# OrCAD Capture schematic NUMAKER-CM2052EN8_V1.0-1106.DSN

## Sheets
1 Nu-Link2-Me: size A3; title: Nu-Link2-Me; rev: 1.0; company: CMHuang; note: Nu-Link2-Me
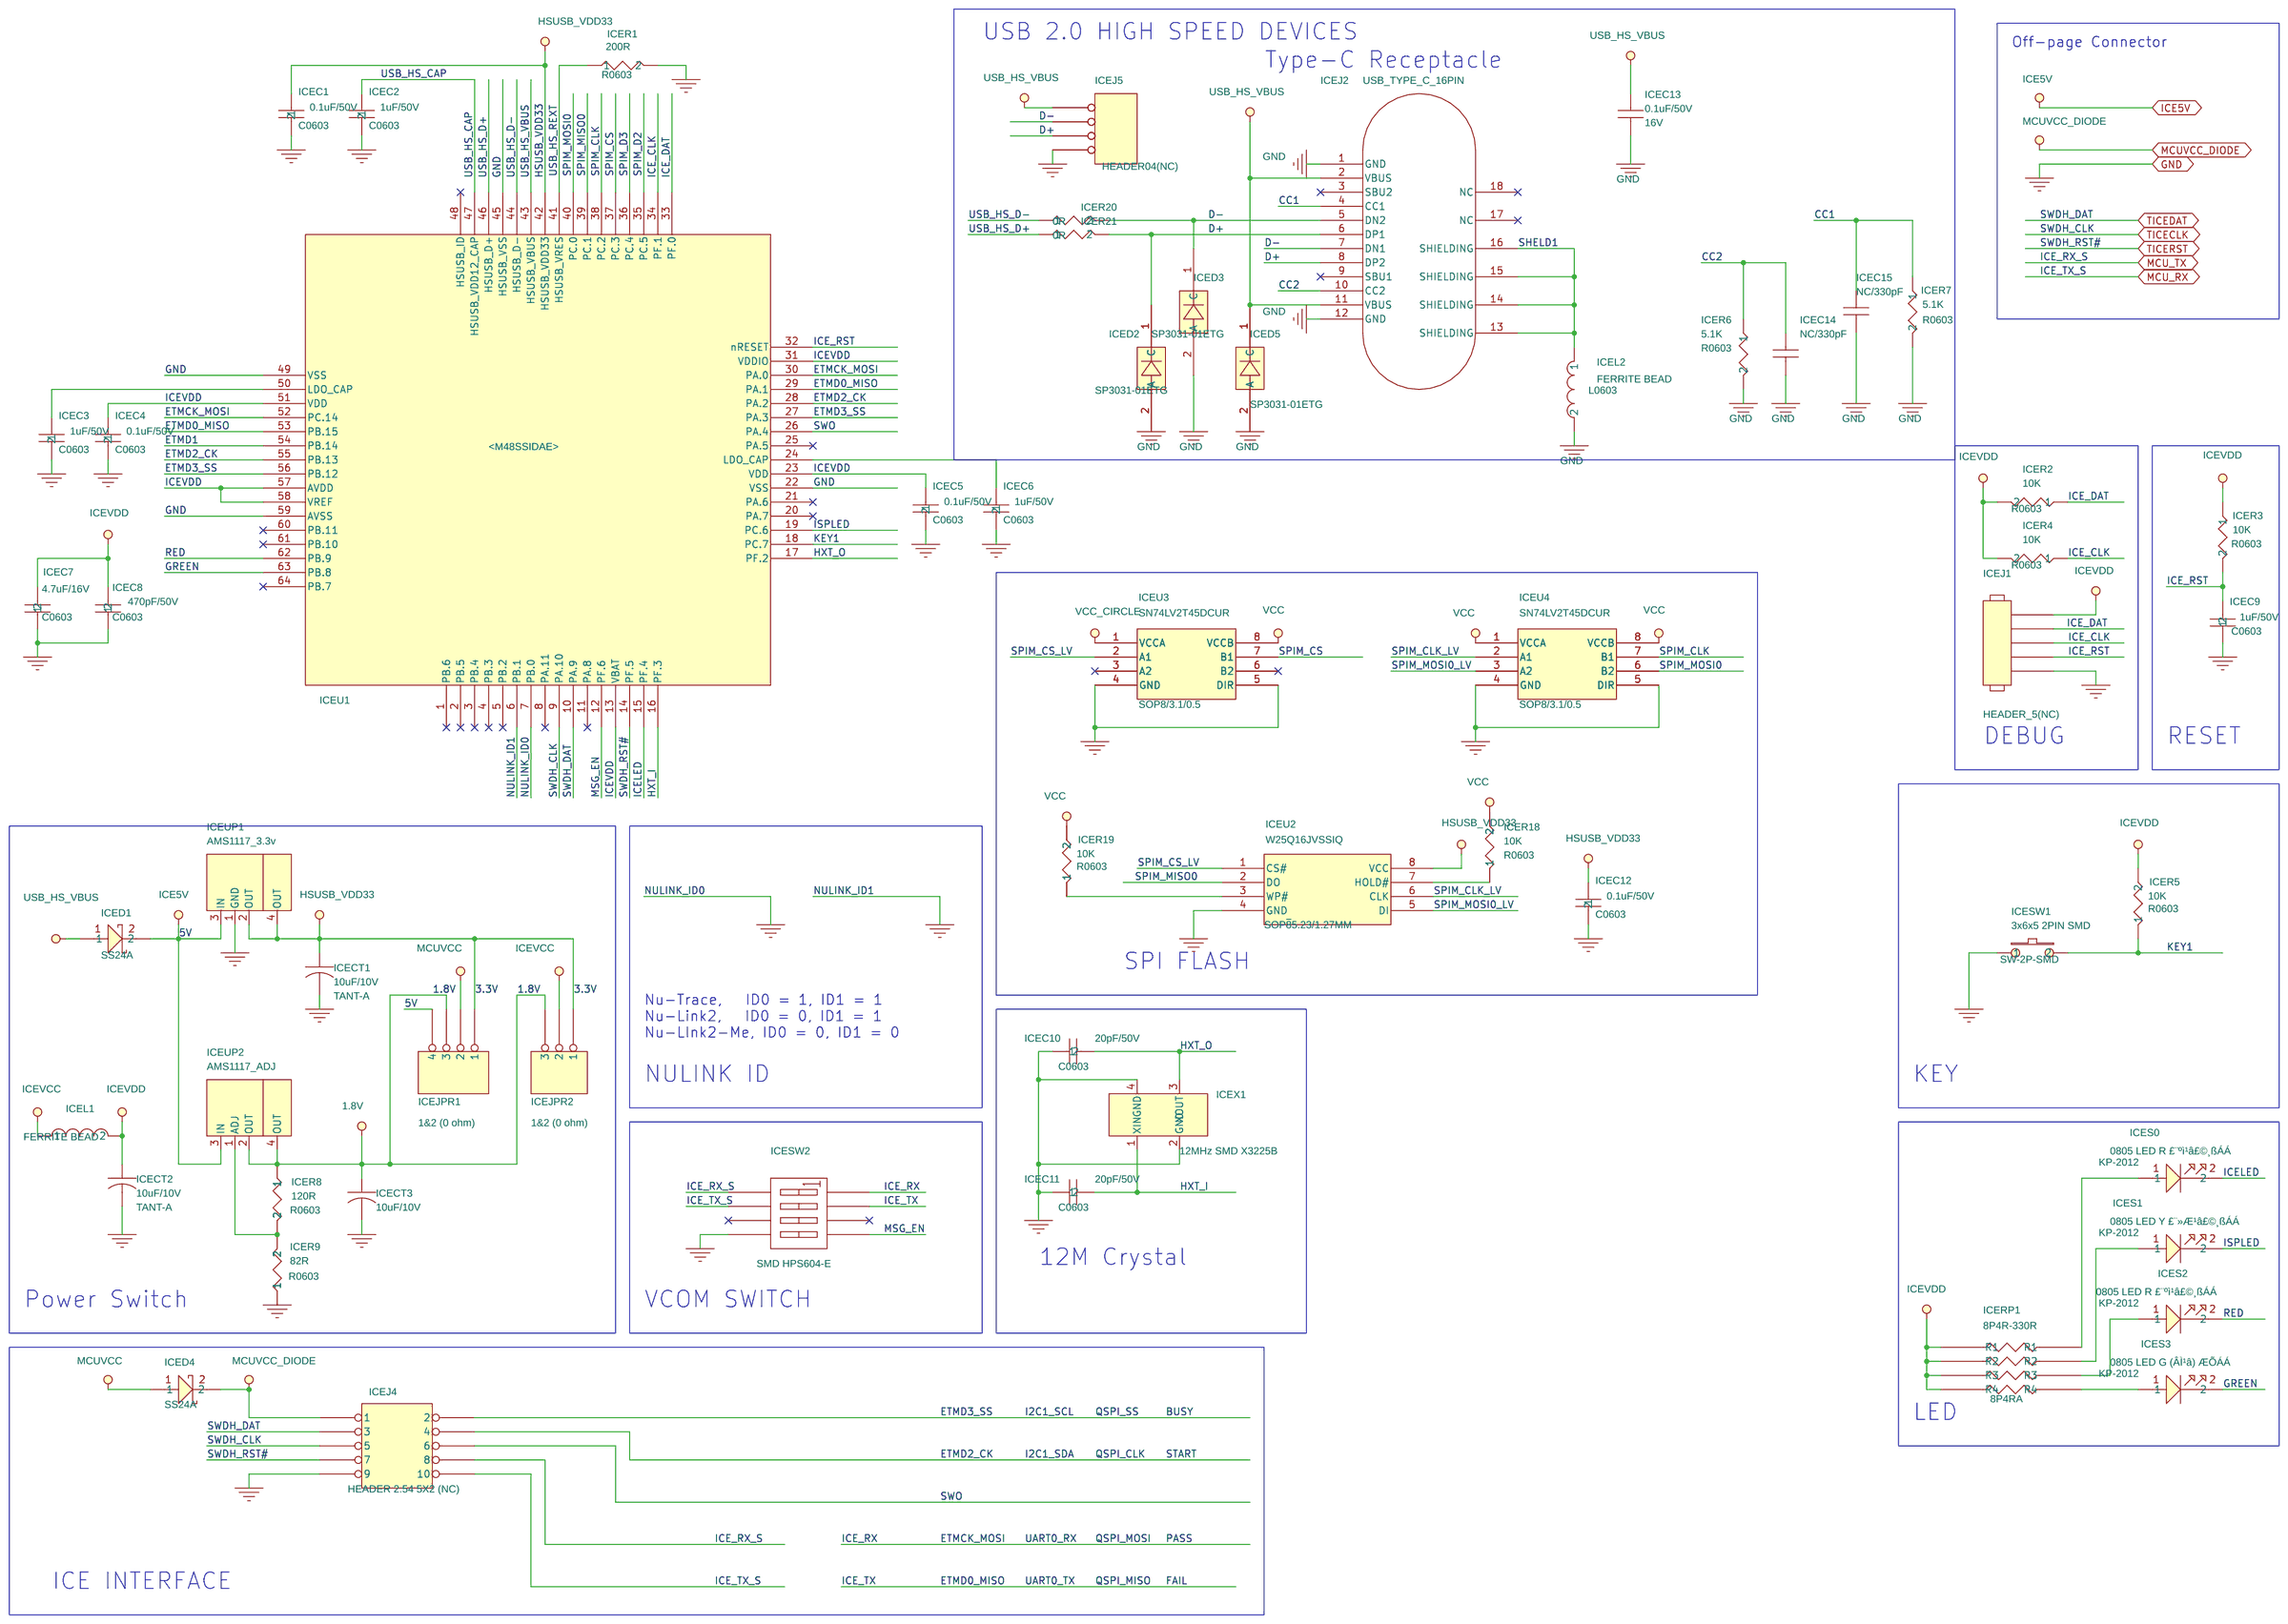
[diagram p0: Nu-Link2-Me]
2 CM2052EN8: size Custom; title: CM2052EN8; rev: v1.0; note: NuMaker-PFM-CM2052EN8
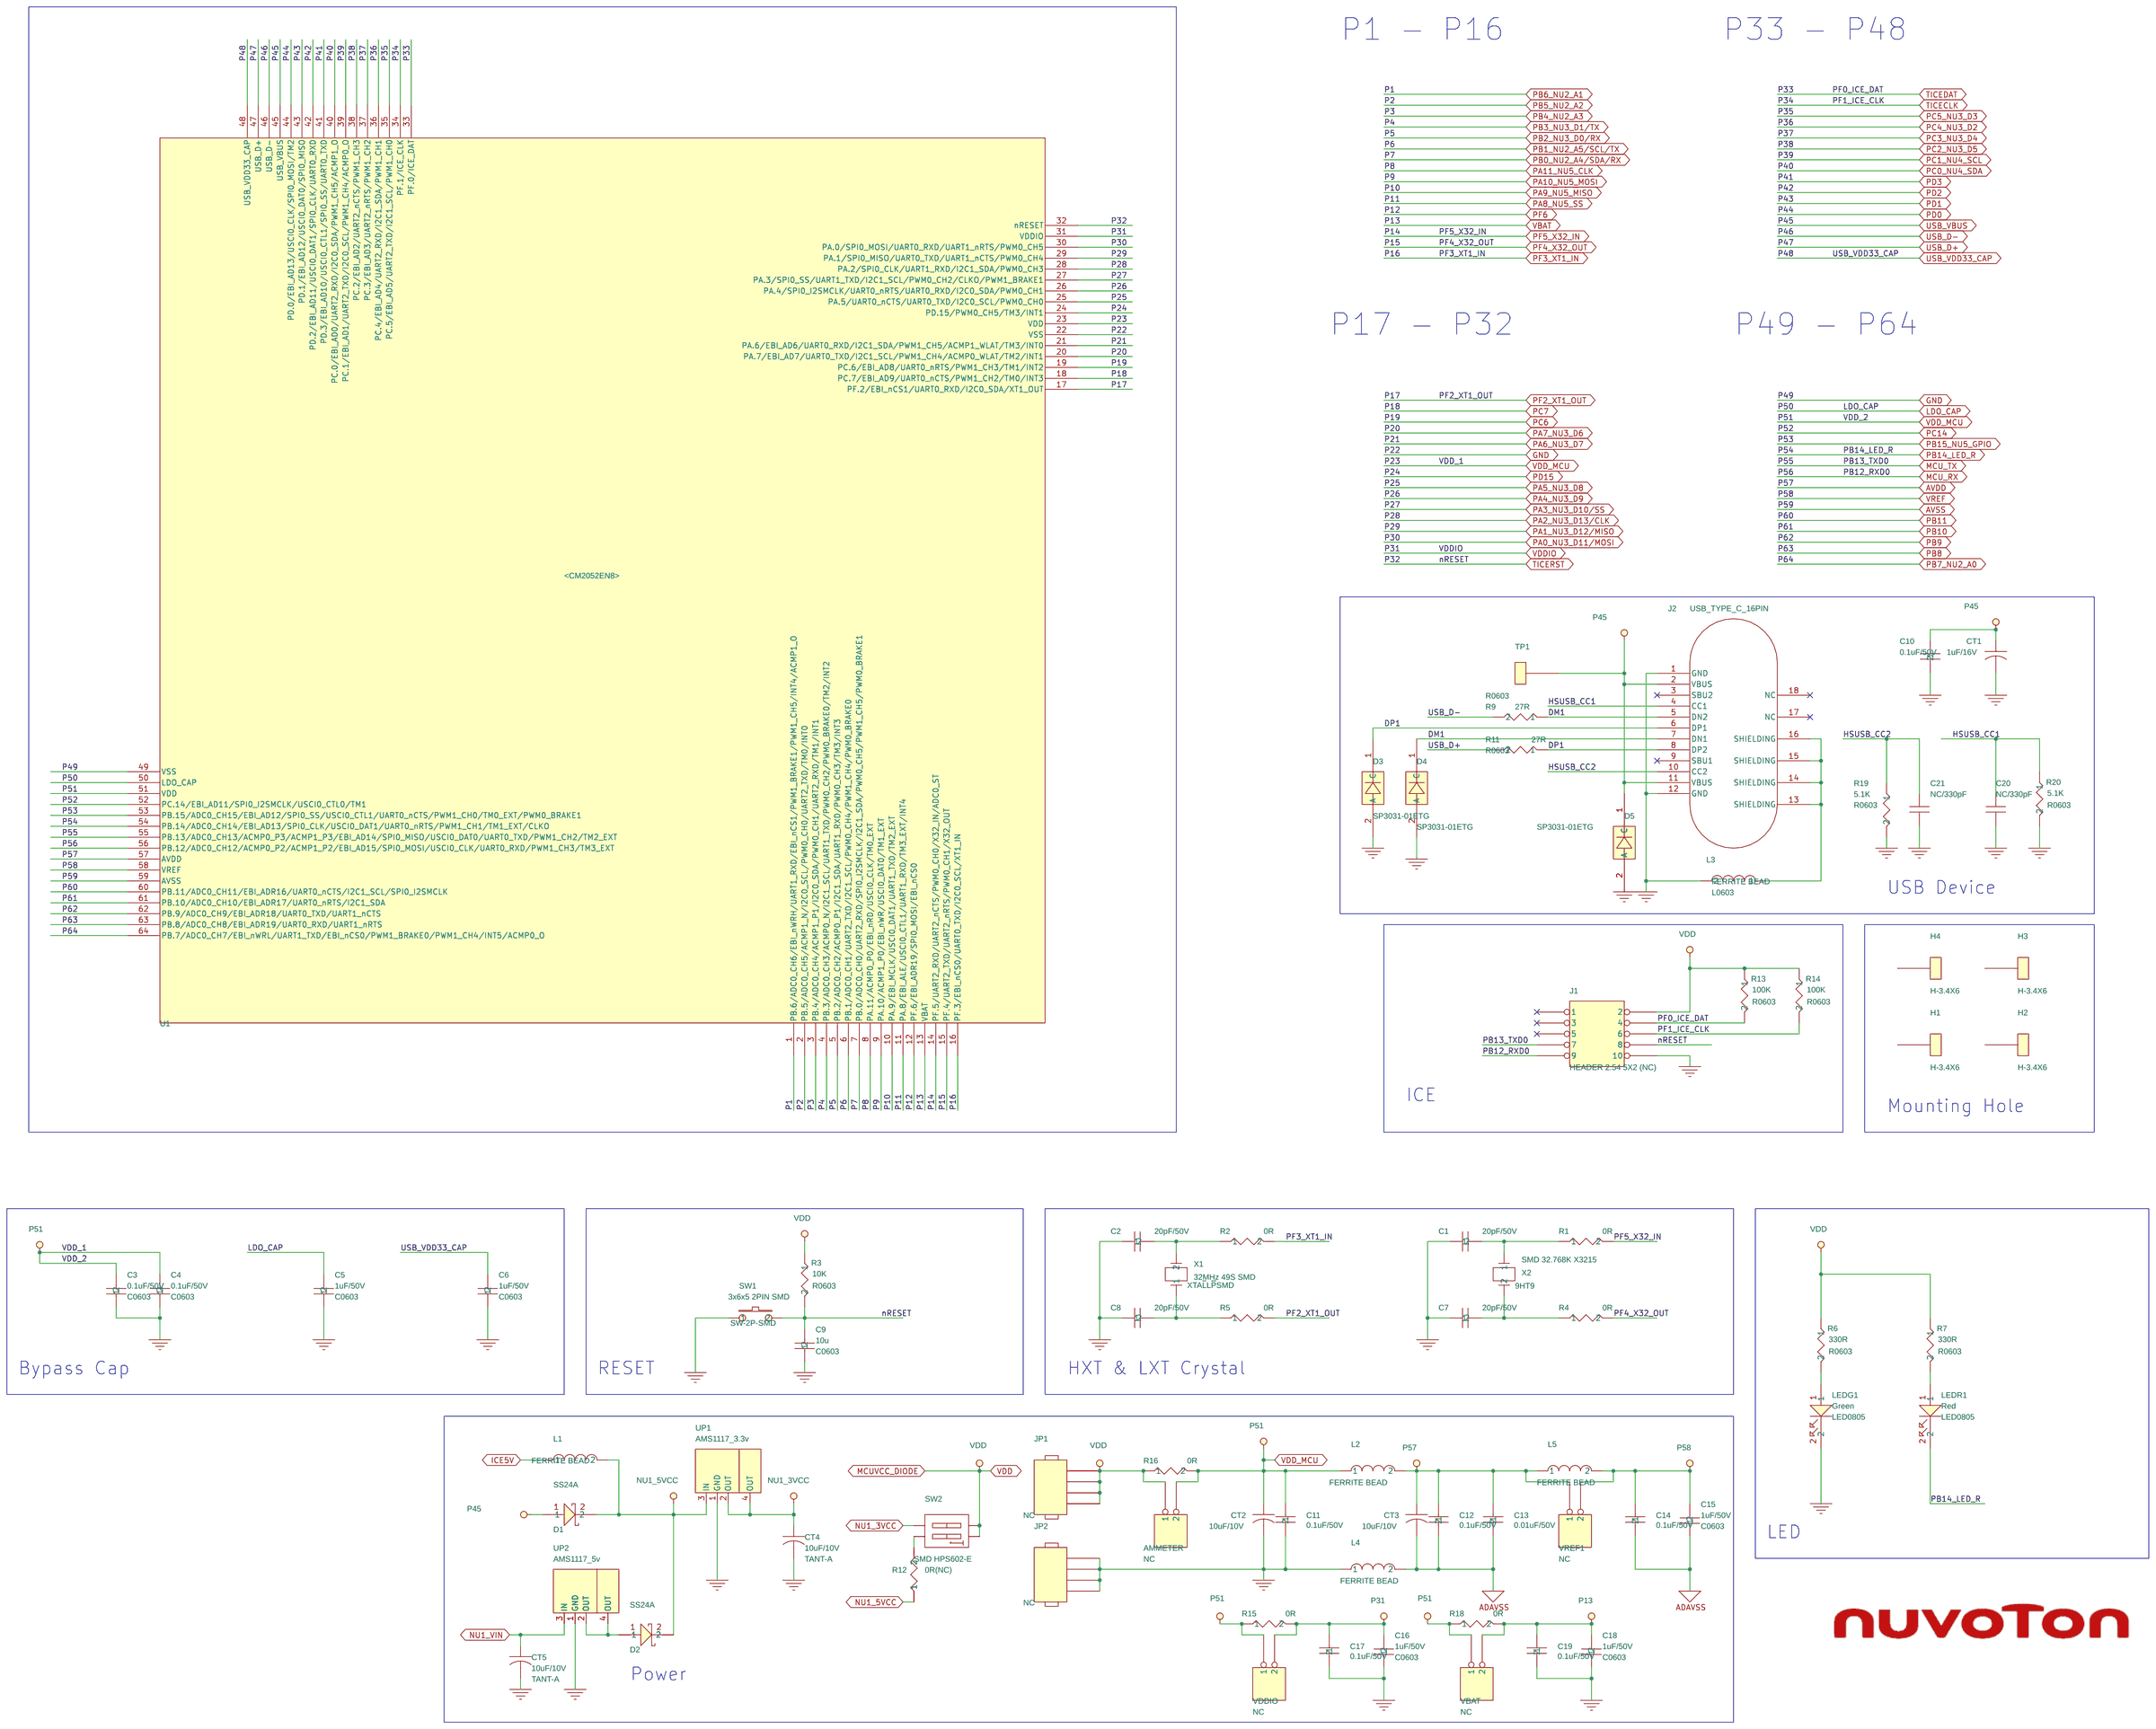
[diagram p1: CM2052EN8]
3 Ext. Connector: size Custom; title: Ext. Connector; rev: v1.0; note: NuMaker-PFM-CM2052EN8
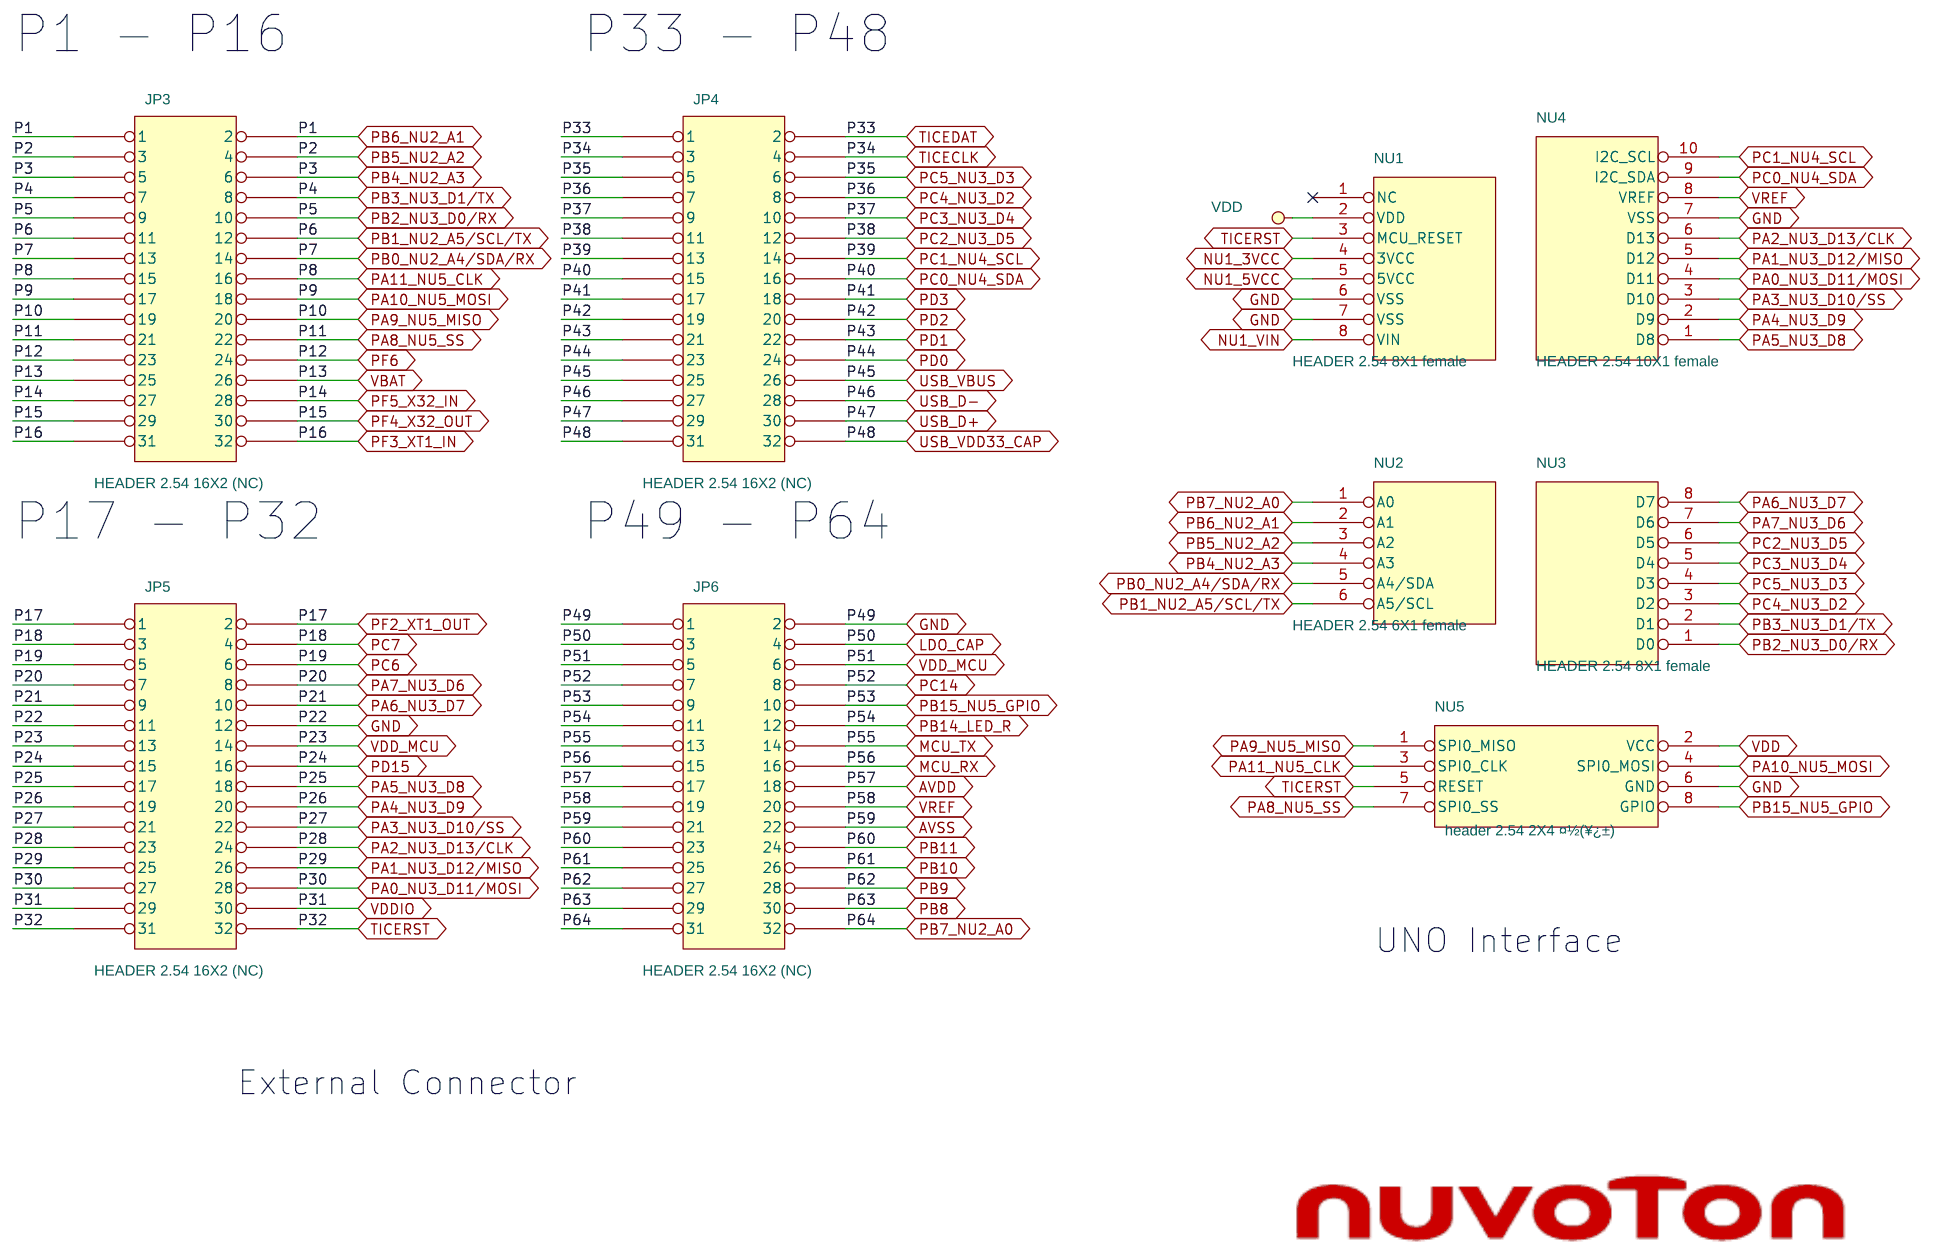
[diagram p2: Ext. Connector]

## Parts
sheet CM2052EN8
AMMETER  NC  [HEADER2X1]
C1  20pF/50V  [C0603]
C2  20pF/50V  [C0603]
C3  0.1uF/50V  [C0603]
C4  0.1uF/50V  [C0603]
C5  1uF/50V  [C0603]
C6  1uF/50V  [C0603]
C7  20pF/50V  [C0603]
C8  20pF/50V  [C0603]
C9  10u  [C0603]
C10  0.1uF/50V  [C0603]
C11  0.1uF/50V  [C0603]
C12  0.1uF/50V  [C0603]
C13  0.01uF/50V  [C0603]
C14  0.1uF/50V  [C0603]
C15  1uF/50V  [C0603]
C16  1uF/50V  [C0603]
C17  0.1uF/50V  [C0603]
C18  1uF/50V  [C0603]
C19  0.1uF/50V  [C0603]
C20  NC/330pF  [C0603]
C21  NC/330pF  [C0603]
CT1  1uF/16V  [TANT-A]
CT2  10uF/10V  [TANT-A]
CT3  10uF/10V  [TANT-A]
CT4  10uF/10V  [TANT-A]
CT5  10uF/10V  [TANT-A]
D1  SS24A  [RB060L]
D2  SS24A  [RB060L]
D3  SP3031-01ETG  [SOD882]
D4  SP3031-01ETG  [SOD882]
D5  SP3031-01ETG  [SOD882]
H1  H-3.4X6  [H-3.4X6]
H2  H-3.4X6  [H-3.4X6]
H3  H-3.4X6  [H-3.4X6]
H4  H-3.4X6  [H-3.4X6]
J1  HEADER 2.54 5X2 (NC)  [HEADER5X2]
J2  USB_TYPE_C_16PIN  [TID(00302-UCAF003-N)]
JP1  NC  [header1x4]
JP2  NC  [header1x4]
L1  FERRITE BEAD  [L0603]
L2  FERRITE BEAD  [L0603]
L3  FERRITE BEAD  [L0603]
L4  FERRITE BEAD  [L0603]
L5  FERRITE BEAD  [L0603]
LEDG1  Green  [LED0805]
LEDR1  Red  [LED0805]
R1  0R  [R0603]
R2  0R  [R0603]
R3  10K  [R0603]
R4  0R  [R0603]
R5  0R  [R0603]
R6  330R  [R0603]
R7  330R  [R0603]
R9  27R  [R0603]
R11  27R  [R0603]
R12  0R(NC)  [R0603]
R13  100K  [R0603]
R14  100K  [R0603]
R15  0R  [R0603]
R16  0R  [R0603]
R18  0R  [R0603]
R19  5.1K  [R0603]
R20  5.1K  [R0603]
SW1  3x6x5 2PIN SMD  [SW-2P-SMD]
SW2  SMD HPS602-E  [SW1X2]
TP1  TEST_POINT  [TEST_POINT]
U1  M252SD2AE  [MCU_LQFP_64_7x7]
UP1  AMS1117_3.3v  [SOT-223-1]
UP2  AMS1117_5v  [SOT-223-1]
VBAT  NC  [HEADER2X1]
VDDIO  NC  [HEADER2X1]
VREF1  NC  [HEADER2X1]
X1  32MHz 49S SMD  [XTAL\LP\SMD]
X2  SMD 32.768K X3215  [9HT9]
sheet Ext. Connector
JP3  HEADER 2.54 16X2 (NC)  [HEADER16X2]
JP4  HEADER 2.54 16X2 (NC)  [HEADER16X2]
JP5  HEADER 2.54 16X2 (NC)  [HEADER16X2]
JP6  HEADER 2.54 16X2 (NC)  [HEADER16X2]
NU1  HEADER 2.54 8X1 female  [SIP-8P]
NU2  HEADER 2.54 6X1 female  [SIP-6P]
NU3  HEADER 2.54 8X1 female  [SIP-8P]
NU4  HEADER 2.54 10X1 female  [SIP-10P]
NU5  header 2.54 2X4 ¤½(¥¿­±)  [HEADER4X2]
sheet Nu-Link2-Me
ICEC1  0.1uF/50V  [C0603]
ICEC2  1uF/50V  [C0603]
ICEC3  1uF/50V  [C0603]
ICEC4  0.1uF/50V  [C0603]
ICEC5  0.1uF/50V  [C0603]
ICEC6  1uF/50V  [C0603]
ICEC7  4.7uF/16V  [C0603]
ICEC8  470pF/50V  [C0603]
ICEC9  1uF/50V  [C0603]
ICEC10  20pF/50V  [C0603]
ICEC11  20pF/50V  [C0603]
ICEC12  0.1uF/50V  [C0603]
ICEC13  0.1uF/50V  [C0603]
ICEC14  NC/330pF  [C0603]
ICEC15  NC/330pF  [C0603]
ICECT1  10uF/10V  [TANT-A]
ICECT2  10uF/10V  [TANT-A]
ICECT3  10uF/10V  [TANT-A]
ICED1  SS24A  [RB060L]
ICED2  SP3031-01ETG  [SOD882]
ICED3  SP3031-01ETG  [SOD882]
ICED4  SS24A  [RB060L]
ICED5  SP3031-01ETG  [SOD882]
ICEJ1  HEADER_5(NC)  [HEADER5X1]
ICEJ2  USB_TYPE_C_16PIN  [TID(00302-UCAF003-N)]
ICEJ4  HEADER 2.54 5X2 (NC)  [HEADER5X2]
ICEJ5  HEADER04(NC)  [HEADER04]
ICEJPR1  1&2 (0 ohm)  [R0603X3]
ICEJPR2  1&2 (0 ohm)  [R0603X2]
ICEL1  FERRITE BEAD  [L0603]
ICEL2  FERRITE BEAD  [L0603]
ICER1  200R  [R0603]
ICER2  10K  [R0603]
ICER3  10K  [R0603]
ICER4  10K  [R0603]
ICER5  10K  [R0603]
ICER6  5.1K  [R0603]
ICER7  5.1K  [R0603]
ICER8  120R  [R0603]
ICER9  82R  [R0603]
ICER18  10K  [R0603]
ICER19  10K  [R0603]
ICER20  0R  [R0603]
ICER21  0R  [R0603]
ICERP1  8P4R-330R  [8P4RA]
ICES0  0805 LED R £¨ºì¹â£©¸ßÁÁ  [KP-2012]
ICES1  0805 LED Y £¨»Æ¹â£©¸ßÁÁ  [KP-2012]
ICES2  0805 LED R £¨ºì¹â£©¸ßÁÁ  [KP-2012]
ICES3  0805 LED G (ÂÌ¹â) ÆÕÁÁ  [KP-2012]
ICESW1  3x6x5 2PIN SMD  [SW-2P-SMD]
ICESW2  SMD HPS604-E  [SW1X4]
ICEU1  M48SSIDAE  [LQFP64_7x7_M48SSIDAE]
ICEU2  W25Q16JVSSIQ  [SOP8\5.23/1.27MM]
ICEU3  SN74LV2T45DCUR  [SOP8/3.1/0.5]
ICEU4  SN74LV2T45DCUR  [SOP8/3.1/0.5]
ICEUP1  AMS1117_3.3v  [SOT-223-1]
ICEUP2  AMS1117_ADJ  [SOT-223-1]
ICEX1  12MHz SMD X3225B  [CRYSTAL_SMD]

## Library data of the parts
AMMETER = HEADER_2_1
C1 = C_20p_3
C2 = C_20p
C3 = CAP-C_5: Package: 0603; element_no: C0004
C4 = CAP-C: Package: 0603; element_no: C0004
C5 = CAP-C_3: Package: 0603; element_no: C0006
C6 = CAP-C_2: Package: 0603; element_no: C0006
C7 = C_20p_1
C8 = C_20p_2
C9 ICEC9 = CAP-C_6: Package: 0603; element_no: C0006
C10 = C_0.1u_3: element_no: C0004
C11 = C_0.1u: element_no: C0004
C12 = C_0.1u_2: element_no: C0004
C13 = C_0.1u_6: element_no: C0003
C14 = C_0.1u_1: element_no: C0004
C15 ICEC6 = CAP-C_4: Package: 0603; element_no: C0006
C16 = CAP-C_7: Package: 0603; element_no: C0006
C17 = C_0.1u_4: element_no: C0004
C18 = CAP-C_1: Package: 0603; element_no: C0006
C19 = C_0.1u_5: element_no: C0004
C20 C21 ICEC14 ICEC15 = CAPACITOR_NP: CAP CER NPO SMD 330pF 5% 50V 0603; Mount: M; Part Number: 880600252; Part Type: Capacitor\Ceramic; Raing/Power: 50V; Tolerance: 5%
CT1 = C_1uF_16V
CT2-CT5 ICECT1-ICECT3 = C_10uF_10V
D1 ICED1 = D_SS24A
D2 ICED4 = D_SS24A_1
D3-D5 ICED2 ICED3 ICED5 = Schottky_Barrier_Diode_1: Diode SMD Schottky Barrier 30V; Mount: M; Part Number: 880900908
H1-H4 TP1 = TEST_POINT
ICEJ4 J1 = HEADER_5X2
ICEJ2 J2 = USB_TYPE_C_10: CON USB 3.0 Type C receptical SMD & TH; Mount: M; Part Number: 880400981; Part Type: Connector
JP1 JP2 = HEADER_4_v2
L1 = FERRITE_BEAD_3
L2 = FERRITE_BEAD_4
L3 = FERRITE_BEAD_2
ICEL2 L4 = FERRITE_BEAD_1
ICEL1 L5 = FERRITE_BEAD
LEDG1 = LED_0_1: Package: KP-2012; Vendor: Kingbright
LEDR1 = LED_0: Package: KP-2012; Vendor: Kingbright
R1 = R_0_1
R2 = R_0_8
ICER9 R3 = R_0_9: Package: 0603
R4 = R_0_16
R5 = R_0_5
R6 = R_0_13: Package: 0603
ICER7 R7 = R_0: Package: 0603
R9 = R_0_10
R11 = R_0_2
R12 = R_0_4
R13 = R_0_12: Package: 0603
R14 = R_0_14: Package: 0603
R15 = R_0_11
R16 = R_0_15
R18 = R_0_3
ICER18 R19 = R_0_7: Package: 0603
ICER1 R20 = R_0_6: Package: 0603
ICESW1 SW1 = SW_PUSHBUTTON_0
SW2 = SW_DIP-4_2
U1 = M031SE3AE_1: M031SE3AE: <CM2052EN8>
ICEUP1 UP1 UP2 = TO-247_Regulator_10
VBAT = HEADER_2_2
VDDIO = HEADER_2_3
VREF1 = HEADER_2
X1 = Xtal_12MHz
X2 = Xtal_32.768K
JP3 = HEADER_16X2_2
JP4 = HEADER_16X2
JP5 = HEADER_16X2_3
JP6 = HEADER_16X2_1
NU1 = POWER_CONNECT_0
NU2 = ADC_CONNECT_0
NU3 = PWM0_CONNECT_0
NU4 = PWM1_CONNECT_1
NU5 = NuEdu_NU7
ICEC1 = CAP-C_8: Package: 0603; element_no: C0004
ICEC2 = CAP-C_9: Package: 0603; element_no: C0006
ICEC3 = CAP-C_10: Package: 0603; element_no: C0006
ICEC4 = CAP-C_1: Package: 0603; element_no: C0004
ICEC5 = CAP-C_3: Package: 0603; element_no: C0004
ICEC7 = CAP-C: Package: 0603
ICEC8 = CAP-C_5: Package: 0603
ICEC10 = CAP-C_2: Package: 0603
ICEC11 = CAP-C_11: Package: 0603
ICEC12 = CAP-C_7: Package: 0603; element_no: C0004
ICEC13 = CAPACITOR_NP: CAP CER X7R SMD 0.1uF 10% 50V 0603; Mount: M; Part Number: 880600286; Part Type: Capacitor\Ceramic; Raing/Power: 16V; Tolerance: 10%
ICEJ1 = HEADER_5
ICEJ5 = HEADER_4
ICEJPR1 = HEADER_3_0
ICEJPR2 = HEADER_3
ICER2 = R_0_1: Package: 0603
ICER3 = R_0_5: Package: 0603
ICER4 = R_0_8: Package: 0603
ICER5 = R_0_3: Package: 0603
ICER6 = R_0_10: Package: 0603
ICER8 = R_0_4: Package: 0603
ICER19 = R_0_2: Package: 0603
ICER20 = R_33_1
ICER21 = R_33
ICERP1 = R-PACK8_0
ICES0 = LED_0_3: Vendor: Kingbright
ICES1 = LED_0_1: Vendor: Kingbright
ICES2 = LED_0: Vendor: Kingbright
ICES3 = LED_0_2: Vendor: Kingbright
ICESW2 = SW_DIP-4_SM
ICEU1 = M487SIDAE_0: M487SIDAE: <M48SSIDAE>
ICEU2 = W25P10_20_40_SOIC_0: Package: SOP8; Vendor: WINBOND
ICEU3 ICEU4 = SN74LV2T45
ICEUP2 = TO-247_Regulator_0
ICEX1 = Crystal_SMD_1

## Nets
1.8V: ICECT3.1 ICEJPR1.3 ICEJPR2.3 ICER8.1 ICEUP2.2(OUT) ICEUP2.4(OUT)
3.3V: ICEC1.1 ICEC12.1 ICECT1.1 ICEJPR1.1 ICEJPR2.1 ICER18.2 ICER19.2 ICEU1.42(HSUSB_VDD33) ICEU2.8(VCC) ICEU3.1(VCCA) ICEU4.1(VCCA) ICEUP1.2(OUT) ICEUP1.4(OUT)
AVDD: C12.1 C13.1 CT3.1 JP6.17 JP6.18 L2.2 L5.1 U1.57(AVDD) VREF1.1
AVSS: C12.2 C13.2 C14.2 C15.1 CT3.2 JP6.21 JP6.22 L4.2 U1.59(AVSS)
GND: C1.1 C2.1 C3.1 C4.1 C5.1 C6.1 C7.1 C8.1 C9.1 C10.2 C11.2 C16.1 C17.2 C18.1 C19.2 C20.2 C21.2 CT1.2 CT2.2 CT4.2 CT5.2 D3.2(A) D4.2(A) D5.2(A) ICEC1.2 ICEC2.2 ICEC3.2 ICEC4.2 ICEC5.2 ICEC6.2 ICEC7.1 ICEC8.1 ICEC9.1 ICEC10.1 ICEC11.1 ICEC12.2 ICEC13.2 ICEC14.2 ICEC15.2 ICECT1.2 ICECT2.2 ICECT3.2 ICED2.2(A) ICED3.2(A) ICED5.2(A) ICEJ1.5 ICEJ2.1(GND) ICEJ2.12(GND) ICEJ4.9 ICEJ5.4 ICEL2.2 ICER1.2 ICER6.2 ICER7.2 ICER9.1 ICESW1.1 ICESW2.4(A4) ICEU1.6(PB.1) ICEU1.7(PB.0) ICEU1.22(VSS) ICEU1.45(HSUSB_VSS) ICEU1.49(VSS) ICEU1.59(AVSS) ICEU2.4(GND) ICEU3.4(GND) ICEU3.5(DIR) ICEU4.4(GND) ICEU4.5(DIR) ICEUP1.1(GND) ICEX1.2(GND) ICEX1.4(GND) J1.10 J2.1(GND) J2.12(GND) JP2.1 JP2.2 JP2.3 JP2.4 JP5.11 JP5.12 JP6.1 JP6.2 L3.2 L4.1 LEDG1.2 NU1.6(VSS) NU1.7(VSS) NU4.7(VSS) NU5.6(GND) R19.2 R20.2 SW1.1 U1.22(VSS) U1.49(VSS) UP1.1(GND) UP2.1(GND)
VBAT: C18.2 C19.1 JP3.25 JP3.26 R18.2 U1.13(VBAT) VBAT.2
VDD: AMMETER.1 ICED4.2 ICEJ4.1 J1.2 JP1.1 JP1.2 JP1.3 JP1.4 NU1.2(VDD) NU5.2(VCC) R3.1 R6.1 R7.1 R13.1 R14.1 R16.1 SW2.3(B1) SW2.4(B2)
VDD_MCU: AMMETER.2 C3.2 C4.2 C11.1 CT2.1 JP5.13 JP5.14 JP6.5 JP6.6 L2.1 R15.1 R16.2 R18.1 U1.23(VDD) U1.51(VDD) VBAT.1 VDDIO.1
VDDIO: C16.2 C17.1 JP5.29 JP5.30 R15.2 U1.31(VDDIO) VDDIO.2
BUSY: ICEJ4.2 ICEU1.27(PA.3) ICEU1.56(PB.12)
CC1: ICEC15.1 ICEJ2.4(CC1) ICER7.1
CC2: ICEC14.1 ICEJ2.10(CC2) ICER6.1
D+: ICED2.1(C) ICEJ2.6(DP1) ICEJ2.8(DP2) ICEJ5.3 ICER21.2
D-: ICED3.1(C) ICEJ2.5(DN2) ICEJ2.7(DN1) ICEJ5.2 ICER20.2
DM1: D4.1(C) J2.5(DN2) J2.7(DN1) R9.1
DP1: D3.1(C) J2.6(DP1) J2.8(DP2) R11.1
ETMD1: ICEU1.54(PB.14)
ETMD2_CK: ICEJ4.4 ICEU1.28(PA.2) ICEU1.55(PB.13)
GREEN: ICES3.2 ICEU1.63(PB.8)
HSUSB_CC1: C20.1 J2.4(CC1) R20.1
HSUSB_CC2: C21.1 J2.10(CC2) R19.1
HXT_I: ICEC11.2 ICEU1.16(PF.3) ICEX1.1(XIN)
HXT_O: ICEC10.2 ICEU1.17(PF.2) ICEX1.3(XOUT)
ICE5V: ICED1.2 ICEJPR1.4 ICEUP1.3(IN) ICEUP2.3(IN) L1.1
ICE_CLK: ICEJ1.3 ICER4.1 ICEU1.34(PF.1)
ICE_DAT: ICEJ1.2 ICER2.1 ICEU1.33(PF.0)
ICE_RST: ICEC9.2 ICEJ1.4 ICER3.2 ICEU1.32(nRESET)
ICE_RX: ICESW2.8(B1) ICEU1.30(PA.0) ICEU1.52(PC.14)
ICE_TX: ICESW2.7(B2) ICEU1.29(PA.1) ICEU1.53(PB.15)
ICELED: ICES0.2 ICEU1.15(PF.4)
ICEVCC: ICEJPR2.2 ICEL1.1
ICEVDD: ICEC4.1 ICEC5.1 ICEC7.2 ICEC8.2 ICECT2.1 ICEJ1.1 ICEL1.2 ICER2.2 ICER3.1 ICER4.2 ICER5.2 ICERP1.1(R1) ICERP1.3(R2) ICERP1.5(R3) ICERP1.7(R4) ICEU1.13(VBAT) ICEU1.23(VDD) ICEU1.31(VDDIO) ICEU1.51(VDD) ICEU1.57(AVDD) ICEU1.58(VREF) ICEU3.8(VCCB) ICEU4.8(VCCB)
ISPLED: ICES1.2 ICEU1.19(PC.6)
KEY1: ICER5.1 ICESW1.2 ICEU1.18(PC.7)
LDO_CAP: C5.2 JP6.3 JP6.4 U1.50(LDO_CAP)
MCU_RX: ICEJ4.10 ICESW2.2(A2) J1.9 JP6.15 JP6.16 U1.56(PB.12/ADC0_CH12/ACMP0_P2/ACMP1_P2/EBI_AD15/SPI0_MOSI/USCI0_CLK/UART0_RXD/PWM1_CH3/TM3_EXT)
MCU_TX: ICEJ4.8 ICESW2.1(A1) J1.7 JP6.13 JP6.14 U1.55(PB.13/ADC0_CH13/ACMP0_P3/ACMP1_P3/EBI_AD14/SPI0_MISO/USCI0_DAT0/UART0_TXD/PWM1_CH2/TM2_EXT)
MCUVCC: ICED4.1 ICEJPR1.2
MSG_EN: ICESW2.5(B4) ICEU1.12(PF.6)
NU1_3VCC: CT4.1 NU1.4(3VCC) SW2.2(A2) UP1.2(OUT) UP1.4(OUT)
NU1_5VCC: D1.2 D2.2 L1.2 NU1.5(5VCC) R12.1 UP1.3(IN)
NU1_VIN: CT5.1 NU1.8(VIN) UP2.3(IN)
PA0_NU3_D11/MOSI: JP5.27 JP5.28 NU4.4(D11) U1.30(PA.0/SPI0_MOSI/UART0_RXD/UART1_nRTS/PWM0_CH5)
PA1_NU3_D12/MISO: JP5.25 JP5.26 NU4.5(D12) U1.29(PA.1/SPI0_MISO/UART0_TXD/UART1_nCTS/PWM0_CH4)
PA2_NU3_D13/CLK: JP5.23 JP5.24 NU4.6(D13) U1.28(PA.2/SPI0_CLK/UART1_RXD/I2C1_SDA/PWM0_CH3)
PA3_NU3_D10/SS: JP5.21 JP5.22 NU4.3(D10) U1.27(PA.3/SPI0_SS/UART1_TXD/I2C1_SCL/PWM0_CH2/CLKO/PWM1_BRAKE1)
PA4_NU3_D9: JP5.19 JP5.20 NU4.2(D9) U1.26(PA.4/SPI0_I2SMCLK/UART0_nRTS/UART0_RXD/I2C0_SDA/PWM0_CH1)
PA5_NU3_D8: JP5.17 JP5.18 NU4.1(D8) U1.25(PA.5/UART0_nCTS/UART0_TXD/I2C0_SCL/PWM0_CH0)
PA6_NU3_D7: JP5.9 JP5.10 NU3.8(D7) U1.21(PA.6/EBI_AD6/UART0_RXD/I2C1_SDA/PWM1_CH5/ACMP1_WLAT/TM3/INT0)
PA7_NU3_D6: JP5.7 JP5.8 NU3.7(D6) U1.20(PA.7/EBI_AD7/UART0_TXD/I2C1_SCL/PWM1_CH4/ACMP0_WLAT/TM2/INT1)
PA8_NU5_SS: JP3.21 JP3.22 NU5.7(SPI0_SS) U1.11(PA.8/EBI_ALE/USCI0_CTL1/UART1_RXD/TM3_EXT/INT4)
PA9_NU5_MISO: JP3.19 JP3.20 NU5.1(SPI0_MISO) U1.10(PA.9/EBI_MCLK/USCI0_DAT1/UART1_TXD/TM2_EXT)
PA10_NU5_MOSI: JP3.17 JP3.18 NU5.4(SPI0_MOSI) U1.9(PA.10/ACMP1_P0/EBI_nWR/USCI0_DAT0/TM1_EXT)
PA11_NU5_CLK: JP3.15 JP3.16 NU5.3(SPI0_CLK) U1.8(PA.11/ACMP0_P0/EBI_nRD/USCI0_CLK/TM0_EXT)
PB0_NU2_A4/SDA/RX: JP3.13 JP3.14 NU2.5(A4/SDA) U1.7(PB.0/ADC0_CH0/UART2_RXD/SPI0_I2SMCLK/I2C1_SDA/PWM0_CH5/PWM1_CH5/PWM0_BRAKE1)
PB1_NU2_A5/SCL/TX: JP3.11 JP3.12 NU2.6(A5/SCL) U1.6(PB.1/ADC0_CH1/UART2_TXD/I2C1_SCL/PWM0_CH4/PWM1_CH4/PWM0_BRAKE0)
PB2_NU3_D0/RX: JP3.9 JP3.10 NU3.1(D0) U1.5(PB.2/ADC0_CH2/ACMP0_P1/I2C1_SDA/UART1_RXD/PWM0_CH3/TM3/INT3)
PB3_NU3_D1/TX: JP3.7 JP3.8 NU3.2(D1) U1.4(PB.3/ADC0_CH3/ACMP0_N/I2C1_SCL/UART1_TXD/PWM0_CH2/PWM0_BRAKE0/TM2/INT2)
PB4_NU2_A3: JP3.5 JP3.6 NU2.4(A3) U1.3(PB.4/ADC0_CH4/ACMP1_P1/I2C0_SDA/PWM0_CH1/UART2_RXD/TM1/INT1)
PB5_NU2_A2: JP3.3 JP3.4 NU2.3(A2) U1.2(PB.5/ADC0_CH5/ACMP1_N/I2C0_SCL/PWM0_CH0/UART2_TXD/TM0/INT0)
PB6_NU2_A1: JP3.1 JP3.2 NU2.2(A1) U1.1(PB.6/ADC0_CH6/EBI_nWRH/UART1_RXD/EBI_nCS1/PWM1_BRAKE1/PWM1_CH5/INT4/ACMP1_O)
PB7_NU2_A0: JP6.31 JP6.32 NU2.1(A0) U1.64(PB.7/ADC0_CH7/EBI_nWRL/UART1_TXD/EBI_nCS0/PWM1_BRAKE0/PWM1_CH4/INT5/ACMP0_O)
PB8: JP6.29 JP6.30 U1.63(PB.8/ADC0_CH8/EBI_ADR19/UART0_RXD/UART1_nRTS)
PB9: JP6.27 JP6.28 U1.62(PB.9/ADC0_CH9/EBI_ADR18/UART0_TXD/UART1_nCTS)
PB10: JP6.25 JP6.26 U1.61(PB.10/ADC0_CH10/EBI_ADR17/UART0_nRTS/I2C1_SDA)
PB11: JP6.23 JP6.24 U1.60(PB.11/ADC0_CH11/EBI_ADR16/UART0_nCTS/I2C1_SCL/SPI0_I2SMCLK)
PB14_LED_R: JP6.11 JP6.12 LEDR1.2 U1.54(PB.14/ADC0_CH14/EBI_AD13/SPI0_CLK/USCI0_DAT1/UART0_nRTS/PWM1_CH1/TM1_EXT/CLKO)
PB15_NU5_GPIO: JP6.9 JP6.10 NU5.8(GPIO) U1.53(PB.15/ADC0_CH15/EBI_AD12/SPI0_SS/USCI0_CTL1/UART0_nCTS/PWM1_CH0/TM0_EXT/PWM0_BRAKE1)
PC0_NU4_SDA: JP4.15 JP4.16 NU4.9(I2C_SDA) U1.40(PC.0/EBI_AD0/UART2_RXD/I2C0_SDA/PWM1_CH5/ACMP1_O)
PC1_NU4_SCL: JP4.13 JP4.14 NU4.10(I2C_SCL) U1.39(PC.1/EBI_AD1/UART2_TXD/I2C0_SCL/PWM1_CH4/ACMP0_O)
PC2_NU3_D5: JP4.11 JP4.12 NU3.6(D5) U1.38(PC.2/EBI_AD2/UART2_nCTS/PWM1_CH3)
PC3_NU3_D4: JP4.9 JP4.10 NU3.5(D4) U1.37(PC.3/EBI_AD3/UART2_nRTS/PWM1_CH2)
PC4_NU3_D2: JP4.7 JP4.8 NU3.3(D2) U1.36(PC.4/EBI_AD4/UART2_RXD/I2C1_SDA/PWM1_CH1)
PC5_NU3_D3: JP4.5 JP4.6 NU3.4(D3) U1.35(PC.5/EBI_AD5/UART2_TXD/I2C1_SCL/PWM1_CH0)
PC6: JP5.5 JP5.6 U1.19(PC.6/EBI_AD8/UART0_nRTS/PWM1_CH3/TM1/INT2)
PC7: JP5.3 JP5.4 U1.18(PC.7/EBI_AD9/UART0_nCTS/PWM1_CH2/TM0/INT3)
PC14: JP6.7 JP6.8 U1.52(PC.14/EBI_AD11/SPI0_I2SMCLK/USCI0_CTL0/TM1)
PD0: JP4.23 JP4.24 U1.44(PD.0/EBI_AD13/USCI0_CLK/SPI0_MOSI/TM2)
PD1: JP4.21 JP4.22 U1.43(PD.1/EBI_AD12/USCI0_DAT0/SPI0_MISO)
PD2: JP4.19 JP4.20 U1.42(PD.2/EBI_AD11/USCI0_DAT1/SPI0_CLK/UART0_RXD)
PD3: JP4.17 JP4.18 U1.41(PD.3/EBI_AD10/USCI0_CTL1/SPI0_SS/UART0_TXD)
PD15: JP5.15 JP5.16 U1.24(PD.15/PWM0_CH5/TM3/INT1)
PF2_XT1_OUT: JP5.1 JP5.2 R5.2 U1.17(PF.2/EBI_nCS1/UART0_RXD/I2C0_SDA/XT1_OUT)
PF3_XT1_IN: JP3.31 JP3.32 R2.2 U1.16(PF.3/EBI_nCS0/UART0_TXD/I2C0_SCL/XT1_IN)
PF4_X32_OUT: JP3.29 JP3.30 R4.2 U1.15(PF.4/UART2_TXD/UART2_nRTS/PWM0_CH1/X32_OUT)
PF5_X32_IN: JP3.27 JP3.28 R1.2 U1.14(PF.5/UART2_RXD/UART2_nCTS/PWM0_CH0/X32_IN/ADC0_ST)
PF6: JP3.23 JP3.24 U1.12(PF.6/EBI_ADR19/SPI0_MOSI/EBI_nCS0)
RED: ICES2.2 ICEU1.62(PB.9)
SHELD1: ICEJ2.13(SHIELDING) ICEJ2.14(SHIELDING) ICEJ2.15(SHIELDING) ICEJ2.16(SHIELDING) ICEL2.1
SPIM_CLK: ICEU1.38(PC.2) ICEU4.7(B1)
SPIM_CLK_LV: ICEU2.6(CLK) ICEU4.2(A1)
SPIM_CS: ICEU1.37(PC.3) ICEU3.7(B1)
SPIM_CS_LV: ICEU2.1(CS#) ICEU3.2(A1)
SPIM_D2: ICEU1.35(PC.5)
SPIM_D3: ICEU1.36(PC.4)
SPIM_MISO0: ICEU1.39(PC.1) ICEU2.2(DO)
SPIM_MOSI0: ICEU1.40(PC.0) ICEU4.6(B2)
SPIM_MOSI0_LV: ICEU2.5(DI) ICEU4.3(A2)
SWO: ICEJ4.6 ICEU1.26(PA.4)
TICECLK: ICEJ4.5 ICEU1.9(PA.10) J1.6 JP4.3 JP4.4 R14.2 U1.34(PF.1/ICE_CLK)
TICEDAT: ICEJ4.3 ICEU1.10(PA.9) J1.4 JP4.1 JP4.2 R13.2 U1.33(PF.0/ICE_DAT)
TICERST: C9.2 ICEJ4.7 ICEU1.14(PF.5) J1.8 JP5.31 JP5.32 NU1.3(MCU_RESET) NU5.5(RESET) R3.2 SW1.2 U1.32(nRESET)
USB_D+: JP4.29 JP4.30 R11.2 U1.47(USB_D+)
USB_D-: JP4.27 JP4.28 R9.2 U1.46(USB_D-)
USB_HS_CAP: ICEC2.1 ICEU1.47(HSUSB_VDD12_CAP)
USB_HS_D+: ICER21.1 ICEU1.46(HSUSB_D+)
USB_HS_D-: ICER20.1 ICEU1.44(HSUSB_D-)
USB_HS_REXT: ICER1.1 ICEU1.41(HSUSB_VRES)
USB_HS_VBUS: ICEC13.1 ICED1.1 ICED5.1(C) ICEJ2.2(VBUS) ICEJ2.11(VBUS) ICEJ5.1 ICEU1.43(HSUSB_VBUS)
USB_VBUS: C10.1 CT1.1 D1.1 D5.1(C) J2.2(VBUS) J2.11(VBUS) JP4.25 JP4.26 TP1.1 U1.45(USB_VBUS)
USB_VDD33_CAP: C6.2 JP4.31 JP4.32 U1.48(USB_VDD33_CAP)
VREF: C14.1 C15.2 JP6.19 JP6.20 L5.2 NU4.8(VREF) U1.58(VREF) VREF1.2
N16825237: LEDG1.1 R6.2
N16825240: LEDR1.1 R7.2
N16840819: ICEC6.1 ICEU1.24(LDO_CAP)
N16840960: ICEC3.1 ICEU1.50(LDO_CAP)
N17019924: ICER8.2 ICER9.2 ICEUP2.1(ADJ)
N17029977: ICERP1.8(R4) ICES3.1
N17029979: ICERP1.6(R3) ICES2.1
N17030004: ICERP1.4(R2) ICES1.1
N17030010: ICERP1.2(R1) ICES0.1
N17155328: ICER18.1 ICEU2.7(HOLD#)
N17155343: ICER19.1 ICEU2.3(WP#)
N17159369: C8.2 R5.1 X1.1
N17159371: C2.2 R2.1 X1.2
N17159463: C1.2 R1.1 X2.1
N17159465: C7.2 R4.1 X2.2
N17187930: R12.2 SW2.1(A1)
N17187980: D2.1 UP2.2(OUT) UP2.4(OUT)
N17223198: J2.13(SHIELDING) J2.14(SHIELDING) J2.15(SHIELDING) J2.16(SHIELDING) L3.1

Not connected (* = marked no-connect by the designer): H1 1; H2 1; H3 1; H4 1; ICEJ2 3(SBU2)* 9(SBU1)* 17(NC)* 18(NC)*; ICESW2 3(A3)* 6(B3)*; ICEU1 1(PB.6)* 2(PB.5)* 3(PB.4)* 4(PB.3)* 5(PB.2)* 8(PA.11)* 11(PA.8)* 20(PA.7)* 21(PA.6)* 25(PA.5)* 48(HSUSB_ID)* 60(PB.11)* 61(PB.10)* 64(PB.7)*; ICEU3 3(A2)* 6(B2)*; J1 1* 3* 5*; J2 3(SBU2)* 9(SBU1)* 17(NC)* 18(NC)*; NU1 1(NC)*

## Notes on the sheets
sheet 1
- USB 2.0 HIGH SPEED DEVICES
- Type-C Receptacle
- Off-page Connector
- DEBUG
- RESET
- SPI FLASH
- Nu-Trace,   ID0 = 1, ID1 = 1
  Nu-Link2,   ID0 = 0, ID1 = 1
  Nu-LInk2-Me, ID0 = 0, ID1 = 0
- NULINK ID
- KEY
- 12M Crystal
- Power Switch
- VCOM SWITCH
- LED
- ICE INTERFACE
sheet 2
- P1 - P16
- P33 - P48
- P17 - P32
- P49 - P64
- USB Device
- ICE
- Mounting Hole
- Bypass Cap
- RESET
- HXT & LXT Crystal
- LED
- Power
sheet 3
- P1 - P16
- P33 - P48
- P17 - P32
- P49 - P64
- UNO Interface
- External Connector
